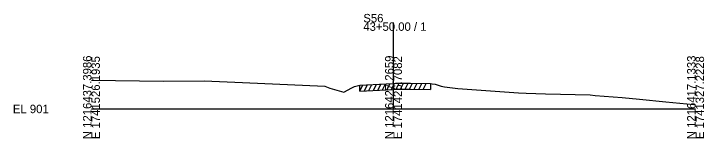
# Model space of a CAD drawing. Extents: x -26 to 1203, y -10 to 19541.
# Drawn here: x -25.7 to 202.8, y 18490.3 to 18531.5 of the extents above; entities that cross this region are included whole.
import ezdxf

# ---------------------------------------------------------------- set-up
doc = ezdxf.new("R2010")
doc.units = 0
for name, color, linetype in [('RD_GPK_XS_Cell', 7, 'Continuous'), ('RD_XS_ExGround', 7, 'Continuous'), ('RD_XS_ExPaveRet', 7, 'Continuous'), ('RD_XS_TX_Elev_EX', 7, 'Continuous')]:
    doc.layers.add(name, color=color, linetype=linetype)

msp = doc.modelspace()

# ---------------------------------------------------------------- linework, layer by layer
at = {"layer": 'RD_GPK_XS_Cell'}
for p, q in [((100, 18500), (100, 18528.68)), ((0, 18500), (100, 18500)), ((100, 18500), (200, 18500))]:
    msp.add_line(p, q, dxfattribs=at)
at = {"layer": 'RD_XS_ExGround'}
msp.add_lwpolyline([(0, 18509.56), (23.83, 18509.19), (37.29, 18509.26), (49.97, 18508.72), (77.31, 18507.59), (78.93, 18506.86), (83.51, 18505.61), (86.22, 18507.01), (87.07, 18507.45), (87.53, 18507.59), (88.84, 18507.92), (97.58, 18508.36), (100, 18508.48), (100.69, 18508.52), (105.63, 18508.55), (112.21, 18508.4), (112.8, 18508.32), (113.79, 18508.17), (115.8, 18507.59), (116.88, 18507.32), (121.27, 18506.78), (141.33, 18505.32), (143.95, 18505.23), (150.35, 18505.05), (165.04, 18504.64), (166.78, 18504.46), (175.7, 18503.75), (181.4, 18503.2), (190.1, 18502.41), (199.46, 18501.43), (200, 18501.38)], dxfattribs=at)
at = {"layer": 'RD_XS_ExPaveRet'}
for p, q in [((88.84, 18505.92), (89.86, 18507.97)), ((88.84, 18505.92), (88.84, 18507.92)), ((90.34, 18506), (91.36, 18508.05)), ((91.84, 18506.07), (92.86, 18508.12)), ((93.34, 18506.15), (94.36, 18508.2)), ((94.84, 18506.22), (95.86, 18508.28)), ((96.34, 18506.3), (97.36, 18508.35)), ((97.84, 18506.37), (98.86, 18508.43)), ((99.34, 18506.45), (100.36, 18508.5)), ((100.84, 18506.52), (101.84, 18508.53)), ((102.34, 18506.53), (103.34, 18508.54)), ((103.84, 18506.54), (104.84, 18508.55)), ((105.34, 18506.55), (106.33, 18508.54)), ((106.84, 18506.52), (107.83, 18508.5)), ((108.34, 18506.49), (109.33, 18508.47)), ((109.84, 18506.45), (110.83, 18508.43)), ((112.21, 18508.4), (112.21, 18506.4)), ((88.84, 18505.92), (97.58, 18506.36)), ((97.58, 18506.36), (100, 18506.48)), ((100, 18506.48), (100.69, 18506.52)), ((100.69, 18506.52), (105.63, 18506.55)), ((105.63, 18506.55), (112.21, 18506.4))]:
    msp.add_line(p, q, dxfattribs=at)

# ---------------------------------------------------------------- texts
at = {"layer": 'RD_GPK_XS_Cell'}
for s, p in [('S56', (90, 18528.68)), ('43+50.00 / 1', (90, 18525.88)), ('EL 901', (-26, 18498.6))]:
    msp.add_text(s, height=2.8, dxfattribs=at).set_placement(p)
for s, p in [('N 1216437.3986', (0, 18490)), ('E 1741526.1935', (2.8, 18490)), ('N 1216427.2659', (100, 18490)), ('E 1741426.7082', (102.8, 18490)), ('N 1216417.1333', (200, 18490)), ('E 1741327.2228', (202.8, 18490))]:
    msp.add_text(s, height=2.8, rotation=90, dxfattribs=at).set_placement(p)
at = {"layer": 'RD_XS_TX_Elev_EX'}
msp.add_text('905.24', height=0.1, rotation=90, dxfattribs=at).set_placement((100.1, 18508.48))

doc.saveas('drawing.dxf')
